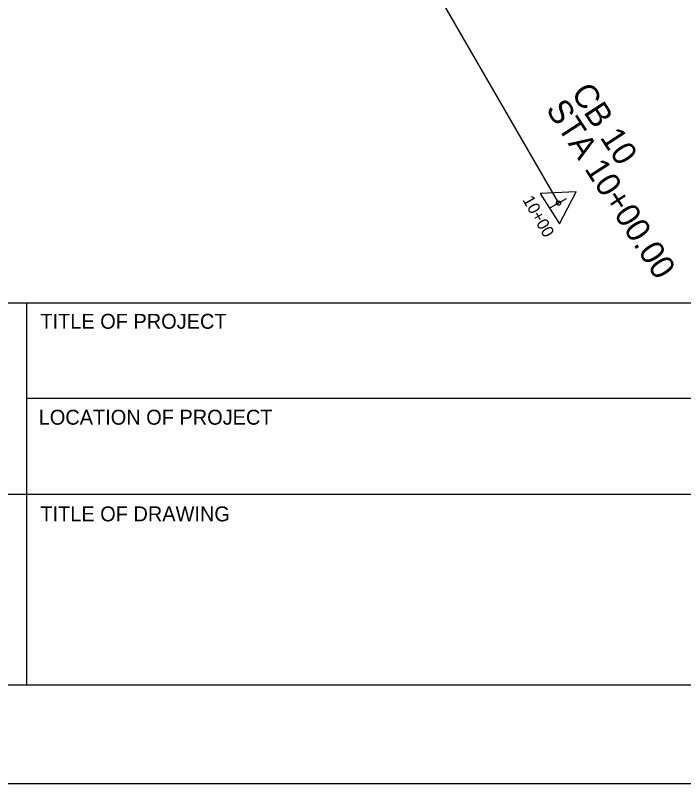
# Model space of a CAD drawing. Extents: x 359002 to 1164845, y 1141798 to 1525369.
# Drawn here: x 1164584.2 to 1164724.2, y 1141797.7 to 1141958.5 of the extents above; entities that cross this region are included whole.
import ezdxf

# ---------------------------------------------------------------- set-up
doc = ezdxf.new("R2010")
doc.units = 0
for name, color, linetype in [('ACSR_P_T', 7, 'Continuous'), ('CB', 7, 'Continuous'), ('CBP', 7, 'Continuous'), ('CBP_C', 7, 'Continuous'), ('SHEET_BORDER', 7, 'Continuous'), ('SHEET_BORDER_EDGE', 7, 'Continuous')]:
    doc.layers.add(name, color=color, linetype=linetype)

msp = doc.modelspace()

# ---------------------------------------------------------------- linework, layer by layer
at = {"layer": 'ACSR_P_T'}
msp.add_lwpolyline([(1164696.28, 1141918.26), (1164699.6, 1141920.19)], dxfattribs=at)
at = {"layer": 'CB'}
msp.add_line((1164291, 1142621.19), (1164697.94, 1141919.22), dxfattribs=at)
at = {"layer": 'CBP'}
for points in [[(1164701.62, 1141921.57), (1164694.07, 1141921.24)], [(1164694.07, 1141921.24), (1164698.13, 1141914.86)], [(1164698.13, 1141914.86), (1164701.62, 1141921.57)]]:
    msp.add_lwpolyline(points, dxfattribs=at)
msp.add_circle((1164697.94, 1141919.22), 0.451, dxfattribs=at)
at = {"layer": 'SHEET_BORDER'}
for p, q in [((1164794.64, 1141898.28), (1164123.01, 1141898.28)), ((1164586.51, 1141898.28), (1164586.51, 1141818.28)), ((1164730.26, 1141878.28), (1164586.51, 1141878.28)), ((1164362.76, 1141858.28), (1164730.26, 1141858.28))]:
    msp.add_line(p, q, dxfattribs=at)
msp.add_lwpolyline([(1164794.64, 1141823.28), (1164789.64, 1141818.28), (1163539.64, 1141818.28), (1163534.64, 1141823.28), (1163534.64, 1142652.02), (1163539.64, 1142657.02), (1164789.64, 1142657.02), (1164794.64, 1142652.02)], close=True, dxfattribs=at)
at = {"layer": 'SHEET_BORDER_EDGE'}
msp.add_lwpolyline([(1163484.64, 1141797.65), (1164844.64, 1141797.65), (1164844.64, 1142677.65), (1163484.64, 1142677.65)], close=True, dxfattribs=at)

# ---------------------------------------------------------------- texts
at = {"layer": 'ACSR_P_T'}
msp.add_text('10+00', height=2.501, rotation=300.1015, dxfattribs=at).set_placement((1164690.32, 1141919.9))
at = {"layer": 'CBP_C'}
for s, height, p in [('CB 10', 5.002, (1164700.45, 1141942.3)), ('STA 10+00.00', 5.0016, (1164695.16, 1141938.87))]:
    msp.add_text(s, height=height, rotation=302.9996, dxfattribs=at).set_placement(p)
at = {"layer": 'SHEET_BORDER'}
for s, p in [('TITLE OF PROJECT', (1164589.4, 1141892.89)), ('LOCATION OF PROJECT', (1164589.05, 1141872.81)), ('TITLE OF DRAWING', (1164589.4, 1141852.57))]:
    msp.add_text(s, height=3.125, rotation=360, dxfattribs=at).set_placement(p)

doc.saveas('drawing.dxf')
